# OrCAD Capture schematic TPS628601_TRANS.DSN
size E; title: TPS628601:1.8-V to 5.5-V Input, 0.6A Synchronous Step-Down; rev: 1.0; note: Datasheet:SLUSDU8B   EVM: SLUUCD1; note: Synchronous Step Down Converter
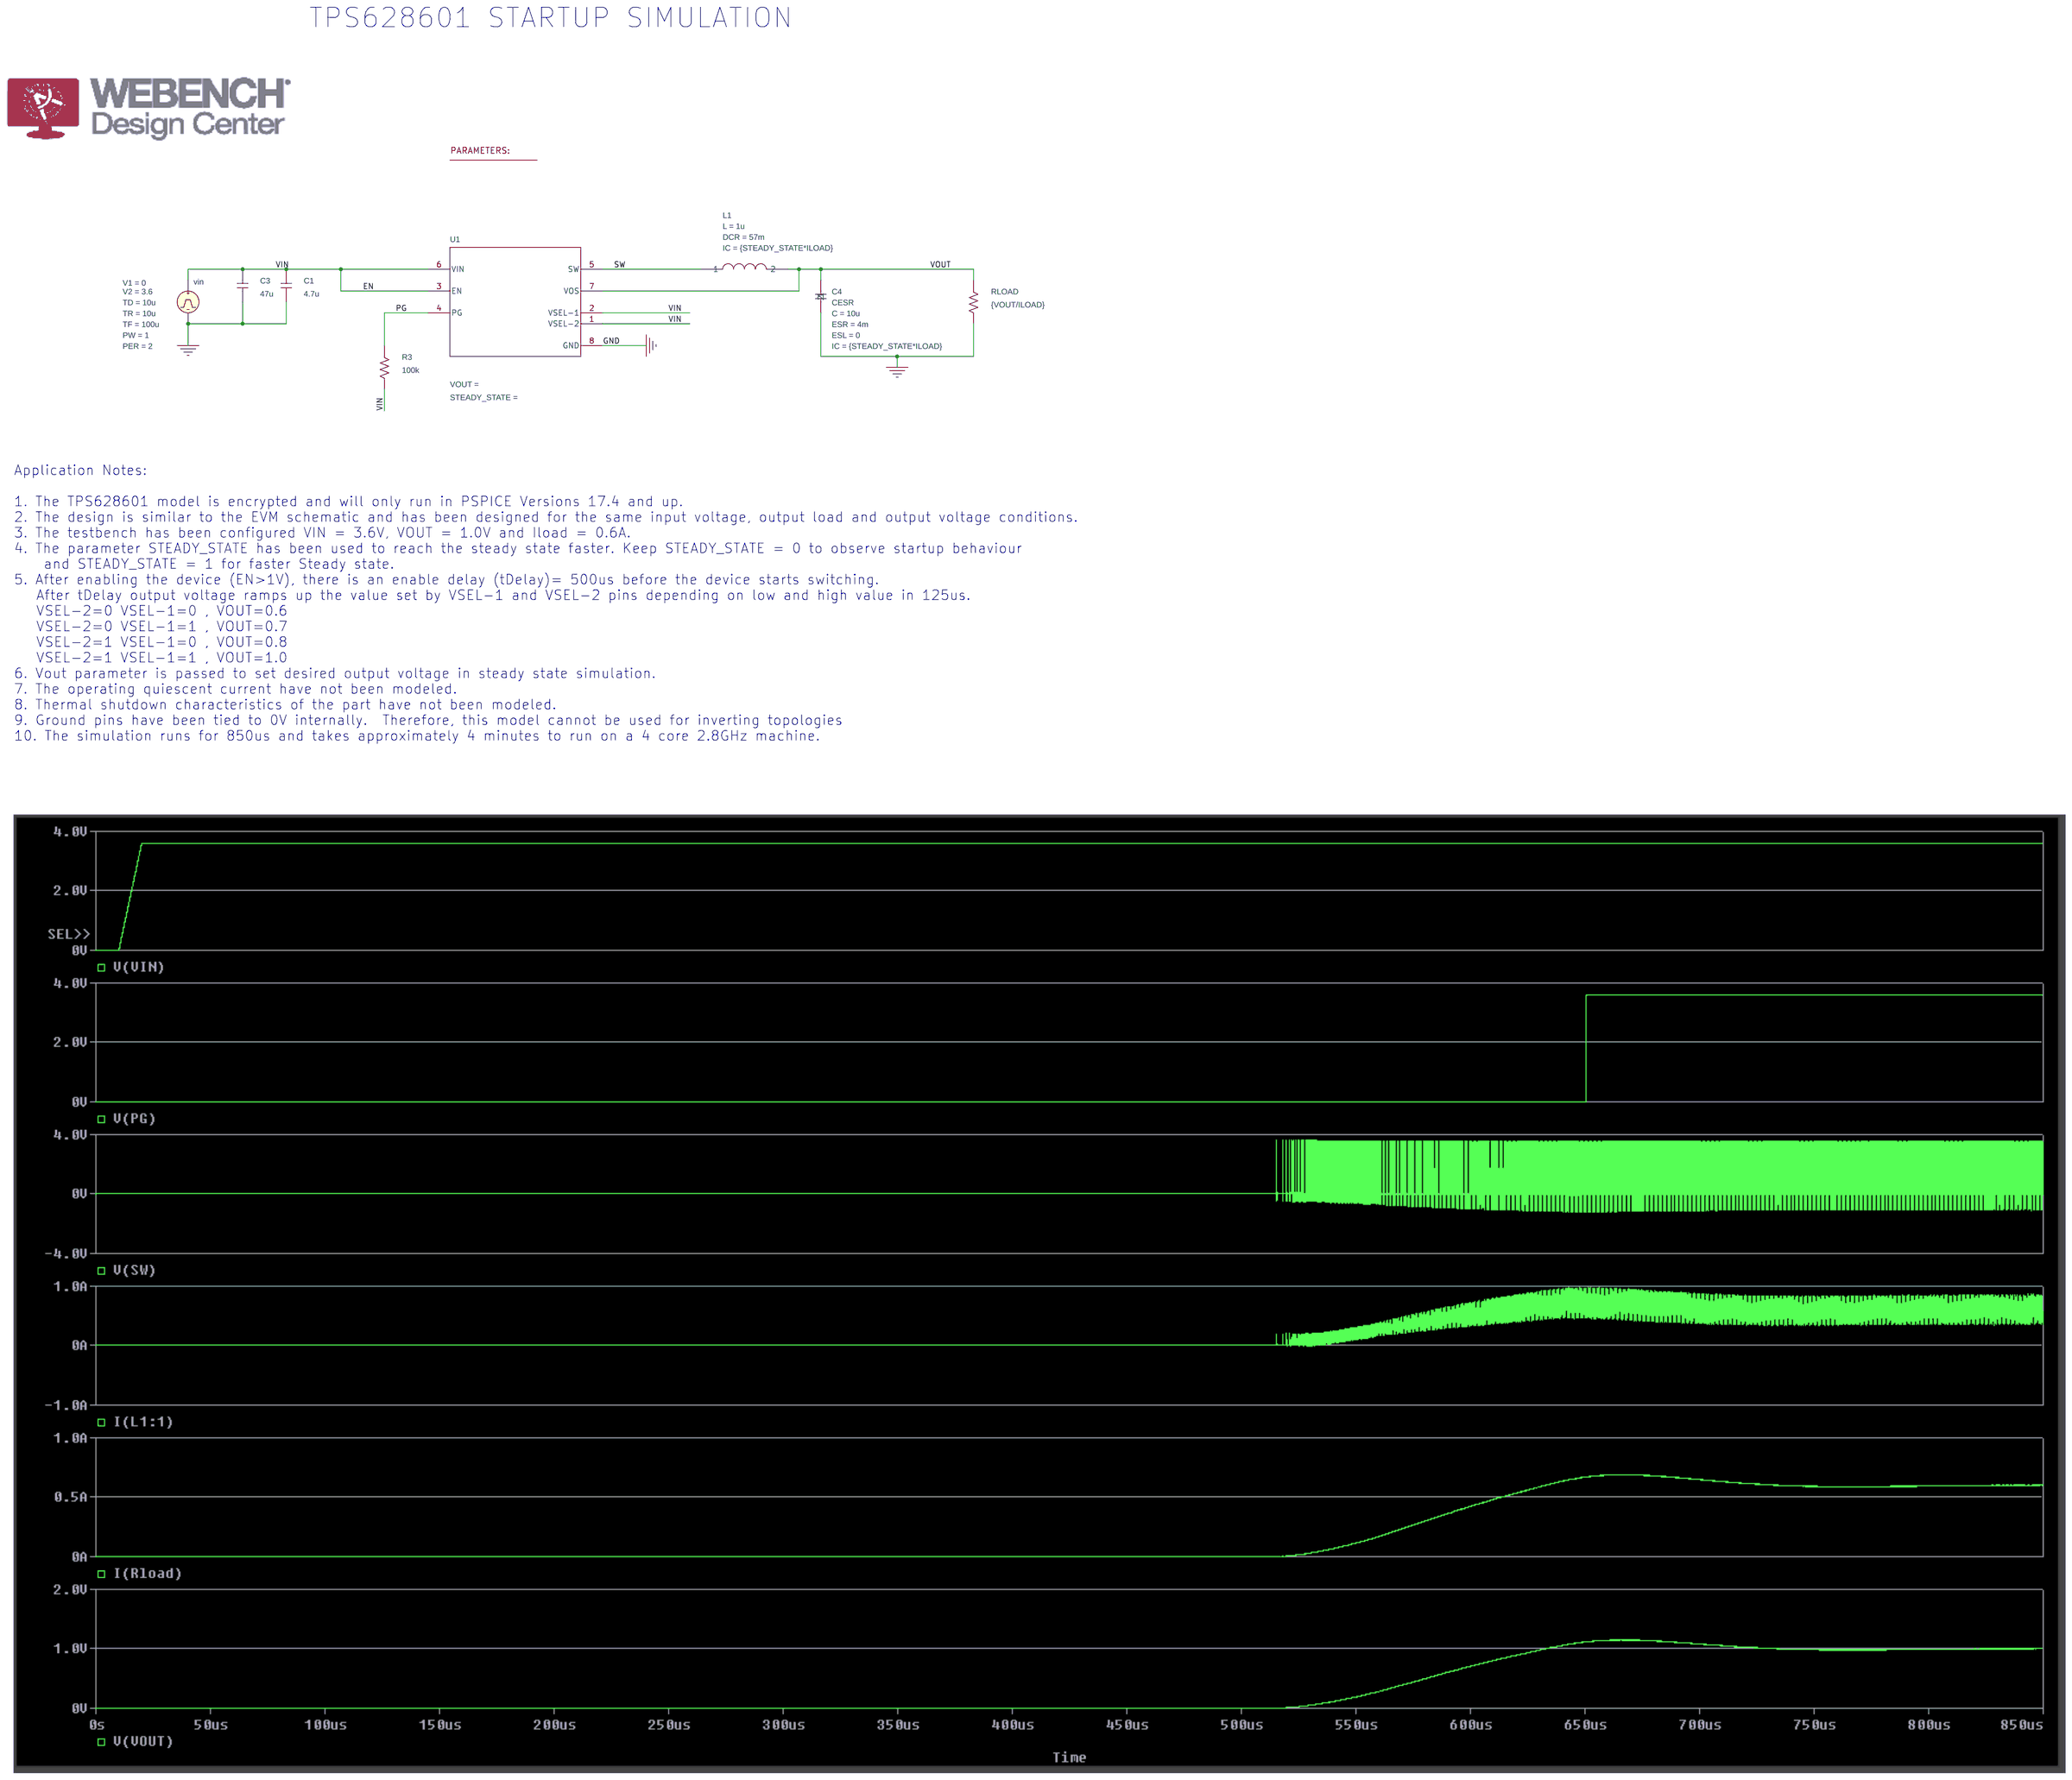
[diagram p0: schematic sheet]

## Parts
2  PARAM
C1  4.7u  [RAD/CK05]
C3  47u  [RAD/CK05]
C4  CESR
L1  LDCR
R3  100k  [AX/RC05]
RLOAD  {VOUT/ILOAD}  [AX/RC05]
U1  TPS628601YCH_TRANS  [YCH0008-IPC_A]
vin  VPULSE

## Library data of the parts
2 = PARAM: ILOAD: 0.6; STEADY_STATE: 0; VOUT: 1
C1 C3 = C
C4 = CESR: C: 10u; ESL: 0; ESR: 4m; IC: {STEADY_STATE*ILOAD}; PSpiceTemplate: X^@REFDES %1 %2 @MODEL PARAMS: ?C|C=@C||C=10U| ?ESR|ESR=@ESR||ESR=2M| ?ESL|ESL=@ESL||ESL=1N| ?IC|IC=@IC||IC=0|
L1 = LDCR: DCR: 57m; IC: {STEADY_STATE*ILOAD}; L: 1u
R3 RLOAD = R
U1 = TPS628601YCH_TRANS
vin = VPULSE: PER: 2; PW: 1; TD: 10u; TF: 100u; TR: 10u; V1: 0; V2: 3.6

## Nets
0: C1.1 C3.1 C4.2 RLOAD.2 U1.8(GND) vin.2(-)
EN: C1.2 C3.2 R3.2 U1.1(VSEL-2) U1.2(VSEL-1) U1.3(EN) U1.6(VIN) vin.1(+)
PG: R3.1 U1.4(PG)
SW: L1.1 U1.5(SW)
VOUT: C4.1 L1.2 RLOAD.1 U1.7(VOS)

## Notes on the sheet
- TPS628601 STARTUP SIMULATION
- Application Notes:
  1. The TPS628601 model is encrypted and will only run in PSPICE Versions 17.4 and up.
  2. The design is similar to the EVM schematic and has been designed for the same input voltage, output load and output voltage conditions.
  3. The testbench has been configured VIN = 3.6V, VOUT = 1.0V and Iload = 0.6A.
  4. The parameter STEADY_STATE has been used to reach the steady state faster. Keep STEADY_STATE = 0 to observe startup behaviour
      and STEADY_STATE = 1 for faster Steady state.
  5. After enabling the device (EN>1V), there is an enable delay (tDelay)= 500us before the device starts switching.
     After tDelay output voltage ramps up the value set by VSEL-1 and VSEL-2 pins depending on low and high value in 125us.
     VSEL-2=0 VSEL-1=0 , VOUT=0.6
     VSEL-2=0 VSEL-1=1 , VOUT=0.7
     VSEL-2=1 VSEL-1=0 , VOUT=0.8
     VSEL-2=1 VSEL-1=1 , VOUT=1.0
  6. Vout parameter is passed to set desired output voltage in steady state simulation.
  7. The operating quiescent current have not been modeled.
  8. Thermal shutdown characteristics of the part have not been modeled.
  9. Ground pins have been tied to 0V internally.  Therefore, this model cannot be used for inverting topologies
  10. The simulation runs for 850us and takes approximately 4 minutes to run on a 4 core 2.8GHz machine.
